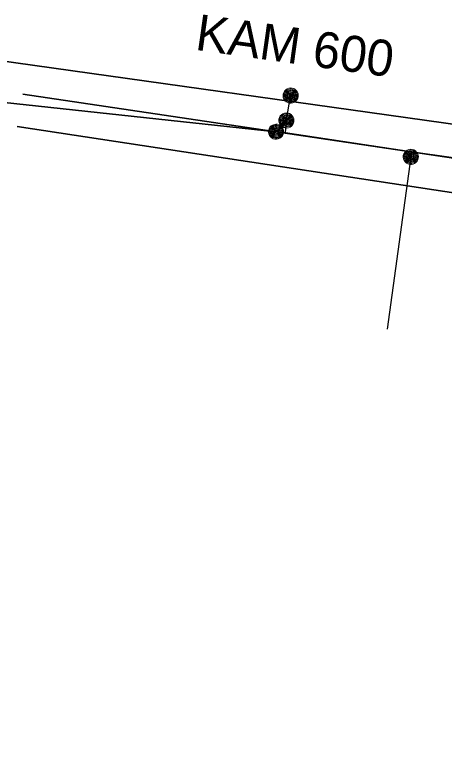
# Model space of a CAD drawing. Extents: x -866761 to -866592, y -1013996 to -1013877.
# Drawn here: x -866735.18 to -866722.08, y -1013979.36 to -1013957.16 of the extents above; entities that cross this region are included whole.
import ezdxf

# ---------------------------------------------------------------- set-up
doc = ezdxf.new("R2010")
doc.units = 0
doc.header["$LTSCALE"] = 0.44
doc.linetypes.add('DOT_DASHED', pattern=[7.7, 5, -1.2, 0.3, -1.2])
for name, color, linetype, lineweight in [('1', 7, 'Continuous', 35), ('12', 7, 'Continuous', 13), ('21', 7, 'Continuous', 35), ('3', 7, 'Continuous', 25), ('8', 7, 'Continuous', 13)]:
    doc.layers.add(name, color=color, linetype=linetype, lineweight=lineweight)

msp = doc.modelspace()

# ---------------------------------------------------------------- linework, layer by layer
at = {"layer": '1'}
msp.add_line((-866612.967, -1013977.763), (-866734.931, -1013959.586), dxfattribs=at)
for points in [[(-866612.815, -1013977.108), (-866621.035, -1013976.325), (-866621.378, -1013976.297), (-866626.243, -1013975.519), (-866632.94, -1013974.51), (-866645.03, -1013972.86), (-866647.305, -1013972.501), (-866654.48, -1013971.31), (-866668.882, -1013969.171), (-866678.229, -1013967.78), (-866685.446, -1013966.718), (-866689.8, -1013966.06), (-866697.865, -1013964.927), (-866723.097, -1013961.352), (-866726.923, -1013960.77), (-866727.214, -1013960.734), (-866737.38, -1013959.64), (-866746.09, -1013958.48), (-866747.84, -1013958.25), (-866748.13, -1013958.99), (-866750.15, -1013958.69)], [(-866613.338, -1013979.363), (-866624.951, -1013977.802), (-866715.256, -1013963.593), (-866735.102, -1013960.577)]]:
    msp.add_lwpolyline(points, dxfattribs=at)
at = {"layer": '1', "linetype": 'DOT_DASHED', "lineweight": 25}
msp.add_lwpolyline([(-866726.923, -1013960.77), (-866726.9, -1013960.39), (-866726.77, -1013959.63)], dxfattribs=at)
at = {"layer": '12'}
for points in [[(-866726.669, -1013960.39), (-866726.675, -1013960.338), (-866726.692, -1013960.288), (-866726.721, -1013960.244), (-866726.758, -1013960.207), (-866726.803, -1013960.18), (-866726.853, -1013960.163), (-866726.906, -1013960.159), (-866726.958, -1013960.166), (-866727.007, -1013960.185), (-866727.05, -1013960.214), (-866727.086, -1013960.253), (-866727.112, -1013960.298), (-866727.128, -1013960.349), (-866727.131, -1013960.401), (-866727.123, -1013960.453), (-866727.103, -1013960.502), (-866727.072, -1013960.545), (-866727.033, -1013960.579), (-866726.987, -1013960.605), (-866726.936, -1013960.619), (-866726.883, -1013960.621), (-866726.832, -1013960.611), (-866726.784, -1013960.59), (-866726.741, -1013960.559), (-866726.707, -1013960.518), (-866726.683, -1013960.472), (-866726.671, -1013960.421)], [(-866726.699, -1013960.39), (-866726.705, -1013960.341), (-866726.722, -1013960.295), (-866726.75, -1013960.255), (-866726.787, -1013960.223), (-866726.831, -1013960.201), (-866726.879, -1013960.19), (-866726.928, -1013960.19), (-866726.975, -1013960.203), (-866727.018, -1013960.227), (-866727.054, -1013960.26), (-866727.081, -1013960.301), (-866727.097, -1013960.348), (-866727.101, -1013960.397), (-866727.094, -1013960.445), (-866727.075, -1013960.49), (-866727.045, -1013960.53), (-866727.007, -1013960.561), (-866726.963, -1013960.581), (-866726.915, -1013960.591), (-866726.866, -1013960.589), (-866726.819, -1013960.574), (-866726.776, -1013960.549), (-866726.742, -1013960.515), (-866726.716, -1013960.473), (-866726.702, -1013960.426)], [(-866726.729, -1013960.39), (-866726.735, -1013960.345), (-866726.752, -1013960.303), (-866726.78, -1013960.268), (-866726.816, -1013960.241), (-866726.858, -1013960.224), (-866726.903, -1013960.219), (-866726.948, -1013960.225), (-866726.989, -1013960.244), (-866727.024, -1013960.272), (-866727.051, -1013960.309), (-866727.067, -1013960.351), (-866727.071, -1013960.396), (-866727.064, -1013960.441), (-866727.045, -1013960.482), (-866727.016, -1013960.516), (-866726.979, -1013960.542), (-866726.936, -1013960.558), (-866726.891, -1013960.561), (-866726.846, -1013960.553), (-866726.806, -1013960.533), (-866726.772, -1013960.504), (-866726.746, -1013960.466), (-866726.732, -1013960.423)], [(-866726.759, -1013960.39), (-866726.764, -1013960.349), (-866726.782, -1013960.312), (-866726.809, -1013960.281), (-866726.844, -1013960.26), (-866726.884, -1013960.249), (-866726.925, -1013960.251), (-866726.964, -1013960.264), (-866726.998, -1013960.288), (-866727.023, -1013960.32), (-866727.038, -1013960.358), (-866727.041, -1013960.399), (-866727.033, -1013960.439), (-866727.013, -1013960.475), (-866726.984, -1013960.504), (-866726.947, -1013960.523), (-866726.907, -1013960.531), (-866726.866, -1013960.527), (-866726.828, -1013960.512), (-866726.796, -1013960.486), (-866726.773, -1013960.452), (-866726.76, -1013960.413)], [(-866726.789, -1013960.39), (-866726.794, -1013960.354), (-866726.812, -1013960.322), (-866726.838, -1013960.297), (-866726.872, -1013960.282), (-866726.908, -1013960.279), (-866726.943, -1013960.287), (-866726.974, -1013960.307), (-866726.997, -1013960.335), (-866727.01, -1013960.369), (-866727.01, -1013960.406), (-866726.999, -1013960.441), (-866726.978, -1013960.47), (-866726.948, -1013960.491), (-866726.913, -1013960.501), (-866726.876, -1013960.499), (-866726.842, -1013960.485), (-866726.815, -1013960.462), (-866726.796, -1013960.43), (-866726.789, -1013960.395)], [(-866726.819, -1013960.39), (-866726.824, -1013960.359), (-866726.841, -1013960.333), (-866726.867, -1013960.316), (-866726.897, -1013960.309), (-866726.928, -1013960.313), (-866726.955, -1013960.33), (-866726.973, -1013960.354), (-866726.981, -1013960.385), (-866726.977, -1013960.415), (-866726.962, -1013960.443), (-866726.938, -1013960.462), (-866726.908, -1013960.471), (-866726.877, -1013960.468), (-866726.849, -1013960.454), (-866726.829, -1013960.43), (-866726.819, -1013960.401)], [(-866726.849, -1013960.39), (-866726.854, -1013960.366), (-866726.871, -1013960.348), (-866726.894, -1013960.339), (-866726.918, -1013960.342), (-866726.939, -1013960.356), (-866726.95, -1013960.378), (-866726.95, -1013960.403), (-866726.938, -1013960.424), (-866726.918, -1013960.438), (-866726.893, -1013960.441), (-866726.87, -1013960.432), (-866726.854, -1013960.414)], [(-866726.879, -1013960.39), (-866726.884, -1013960.375), (-866726.899, -1013960.369), (-866726.914, -1013960.373), (-866726.921, -1013960.387), (-866726.917, -1013960.402), (-866726.904, -1013960.411), (-866726.889, -1013960.408), (-866726.879, -1013960.396)], [(-866726.983, -1013960.734), (-866726.989, -1013960.682), (-866727.006, -1013960.632), (-866727.035, -1013960.588), (-866727.072, -1013960.551), (-866727.117, -1013960.524), (-866727.167, -1013960.507), (-866727.22, -1013960.503), (-866727.272, -1013960.51), (-866727.321, -1013960.529), (-866727.364, -1013960.558), (-866727.4, -1013960.597), (-866727.426, -1013960.642), (-866727.442, -1013960.693), (-866727.445, -1013960.745), (-866727.437, -1013960.797), (-866727.417, -1013960.846), (-866727.386, -1013960.889), (-866727.347, -1013960.923), (-866727.301, -1013960.949), (-866727.25, -1013960.963), (-866727.197, -1013960.965), (-866727.146, -1013960.955), (-866727.098, -1013960.934), (-866727.055, -1013960.903), (-866727.021, -1013960.862), (-866726.997, -1013960.816), (-866726.985, -1013960.765)], [(-866727.013, -1013960.734), (-866727.019, -1013960.685), (-866727.036, -1013960.639), (-866727.064, -1013960.599), (-866727.101, -1013960.567), (-866727.145, -1013960.545), (-866727.193, -1013960.534), (-866727.242, -1013960.534), (-866727.289, -1013960.547), (-866727.332, -1013960.571), (-866727.368, -1013960.604), (-866727.395, -1013960.645), (-866727.411, -1013960.692), (-866727.415, -1013960.741), (-866727.408, -1013960.789), (-866727.389, -1013960.834), (-866727.359, -1013960.874), (-866727.321, -1013960.905), (-866727.277, -1013960.925), (-866727.229, -1013960.935), (-866727.18, -1013960.933), (-866727.133, -1013960.918), (-866727.09, -1013960.893), (-866727.056, -1013960.859), (-866727.03, -1013960.817), (-866727.016, -1013960.77)], [(-866727.043, -1013960.734), (-866727.049, -1013960.689), (-866727.066, -1013960.647), (-866727.094, -1013960.612), (-866727.13, -1013960.585), (-866727.172, -1013960.568), (-866727.217, -1013960.563), (-866727.262, -1013960.569), (-866727.303, -1013960.588), (-866727.338, -1013960.616), (-866727.365, -1013960.653), (-866727.381, -1013960.695), (-866727.385, -1013960.74), (-866727.378, -1013960.785), (-866727.359, -1013960.826), (-866727.33, -1013960.86), (-866727.293, -1013960.886), (-866727.25, -1013960.902), (-866727.205, -1013960.905), (-866727.16, -1013960.897), (-866727.12, -1013960.877), (-866727.086, -1013960.848), (-866727.06, -1013960.81), (-866727.046, -1013960.767)], [(-866727.073, -1013960.734), (-866727.078, -1013960.693), (-866727.096, -1013960.656), (-866727.123, -1013960.625), (-866727.158, -1013960.604), (-866727.198, -1013960.593), (-866727.239, -1013960.595), (-866727.278, -1013960.608), (-866727.312, -1013960.632), (-866727.337, -1013960.664), (-866727.352, -1013960.702), (-866727.355, -1013960.743), (-866727.347, -1013960.783), (-866727.327, -1013960.819), (-866727.298, -1013960.848), (-866727.261, -1013960.867), (-866727.221, -1013960.875), (-866727.18, -1013960.871), (-866727.142, -1013960.856), (-866727.11, -1013960.83), (-866727.087, -1013960.796), (-866727.074, -1013960.757)], [(-866727.103, -1013960.734), (-866727.108, -1013960.698), (-866727.126, -1013960.666), (-866727.152, -1013960.641), (-866727.186, -1013960.626), (-866727.222, -1013960.623), (-866727.257, -1013960.631), (-866727.288, -1013960.651), (-866727.311, -1013960.679), (-866727.324, -1013960.713), (-866727.324, -1013960.75), (-866727.313, -1013960.785), (-866727.292, -1013960.814), (-866727.262, -1013960.835), (-866727.227, -1013960.845), (-866727.19, -1013960.843), (-866727.156, -1013960.829), (-866727.129, -1013960.806), (-866727.11, -1013960.774), (-866727.103, -1013960.739)], [(-866727.133, -1013960.734), (-866727.138, -1013960.703), (-866727.155, -1013960.677), (-866727.181, -1013960.66), (-866727.211, -1013960.653), (-866727.242, -1013960.657), (-866727.269, -1013960.674), (-866727.287, -1013960.698), (-866727.295, -1013960.729), (-866727.291, -1013960.759), (-866727.276, -1013960.787), (-866727.252, -1013960.806), (-866727.222, -1013960.815), (-866727.191, -1013960.812), (-866727.163, -1013960.798), (-866727.143, -1013960.774), (-866727.133, -1013960.745)], [(-866727.163, -1013960.734), (-866727.168, -1013960.71), (-866727.185, -1013960.692), (-866727.208, -1013960.683), (-866727.232, -1013960.686), (-866727.253, -1013960.7), (-866727.264, -1013960.722), (-866727.264, -1013960.747), (-866727.252, -1013960.768), (-866727.232, -1013960.782), (-866727.207, -1013960.785), (-866727.184, -1013960.776), (-866727.168, -1013960.758)], [(-866727.193, -1013960.734), (-866727.198, -1013960.719), (-866727.213, -1013960.713), (-866727.228, -1013960.717), (-866727.235, -1013960.731), (-866727.231, -1013960.746), (-866727.218, -1013960.755), (-866727.203, -1013960.752), (-866727.193, -1013960.74)], [(-866722.879, -1013961.5), (-866722.885, -1013961.448), (-866722.902, -1013961.398), (-866722.931, -1013961.354), (-866722.968, -1013961.317), (-866723.013, -1013961.29), (-866723.063, -1013961.273), (-866723.116, -1013961.269), (-866723.168, -1013961.276), (-866723.217, -1013961.295), (-866723.26, -1013961.324), (-866723.296, -1013961.363), (-866723.322, -1013961.408), (-866723.338, -1013961.459), (-866723.341, -1013961.511), (-866723.333, -1013961.563), (-866723.313, -1013961.612), (-866723.282, -1013961.655), (-866723.243, -1013961.689), (-866723.197, -1013961.715), (-866723.146, -1013961.729), (-866723.093, -1013961.731), (-866723.042, -1013961.721), (-866722.994, -1013961.7), (-866722.951, -1013961.669), (-866722.917, -1013961.628), (-866722.893, -1013961.582), (-866722.88, -1013961.531)], [(-866722.909, -1013961.5), (-866722.915, -1013961.451), (-866722.932, -1013961.405), (-866722.96, -1013961.365), (-866722.997, -1013961.333), (-866723.041, -1013961.311), (-866723.089, -1013961.3), (-866723.138, -1013961.3), (-866723.184, -1013961.313), (-866723.228, -1013961.337), (-866723.264, -1013961.37), (-866723.291, -1013961.411), (-866723.307, -1013961.458), (-866723.311, -1013961.507), (-866723.304, -1013961.555), (-866723.285, -1013961.6), (-866723.255, -1013961.64), (-866723.217, -1013961.671), (-866723.173, -1013961.691), (-866723.125, -1013961.701), (-866723.076, -1013961.699), (-866723.029, -1013961.684), (-866722.986, -1013961.659), (-866722.951, -1013961.625), (-866722.926, -1013961.583), (-866722.912, -1013961.536)], [(-866722.939, -1013961.5), (-866722.945, -1013961.455), (-866722.962, -1013961.413), (-866722.99, -1013961.378), (-866723.026, -1013961.351), (-866723.068, -1013961.334), (-866723.113, -1013961.329), (-866723.157, -1013961.335), (-866723.199, -1013961.354), (-866723.233, -1013961.382), (-866723.261, -1013961.419), (-866723.277, -1013961.461), (-866723.281, -1013961.506), (-866723.274, -1013961.551), (-866723.255, -1013961.592), (-866723.226, -1013961.626), (-866723.189, -1013961.652), (-866723.146, -1013961.668), (-866723.101, -1013961.671), (-866723.056, -1013961.663), (-866723.016, -1013961.643), (-866722.982, -1013961.614), (-866722.956, -1013961.576), (-866722.942, -1013961.533)], [(-866722.969, -1013961.5), (-866722.973, -1013961.459), (-866722.992, -1013961.422), (-866723.019, -1013961.391), (-866723.054, -1013961.37), (-866723.094, -1013961.359), (-866723.135, -1013961.361), (-866723.174, -1013961.374), (-866723.208, -1013961.398), (-866723.233, -1013961.43), (-866723.248, -1013961.468), (-866723.25, -1013961.509), (-866723.243, -1013961.549), (-866723.223, -1013961.585), (-866723.194, -1013961.614), (-866723.157, -1013961.633), (-866723.117, -1013961.641), (-866723.076, -1013961.637), (-866723.038, -1013961.622), (-866723.005, -1013961.596), (-866722.983, -1013961.562), (-866722.97, -1013961.523)], [(-866722.999, -1013961.5), (-866723.004, -1013961.464), (-866723.022, -1013961.432), (-866723.048, -1013961.407), (-866723.081, -1013961.392), (-866723.118, -1013961.389), (-866723.152, -1013961.397), (-866723.184, -1013961.417), (-866723.206, -1013961.445), (-866723.22, -1013961.479), (-866723.22, -1013961.516), (-866723.209, -1013961.551), (-866723.188, -1013961.58), (-866723.157, -1013961.601), (-866723.123, -1013961.611), (-866723.086, -1013961.609), (-866723.052, -1013961.595), (-866723.025, -1013961.572), (-866723.005, -1013961.54), (-866722.999, -1013961.505)], [(-866723.029, -1013961.5), (-866723.034, -1013961.469), (-866723.051, -1013961.443), (-866723.076, -1013961.426), (-866723.107, -1013961.419), (-866723.138, -1013961.423), (-866723.165, -1013961.44), (-866723.183, -1013961.464), (-866723.191, -1013961.495), (-866723.187, -1013961.525), (-866723.172, -1013961.553), (-866723.147, -1013961.572), (-866723.118, -1013961.581), (-866723.087, -1013961.578), (-866723.059, -1013961.564), (-866723.039, -1013961.54), (-866723.029, -1013961.511)], [(-866723.059, -1013961.5), (-866723.064, -1013961.476), (-866723.081, -1013961.458), (-866723.103, -1013961.449), (-866723.128, -1013961.452), (-866723.149, -1013961.466), (-866723.16, -1013961.488), (-866723.16, -1013961.513), (-866723.147, -1013961.534), (-866723.128, -1013961.548), (-866723.103, -1013961.551), (-866723.08, -1013961.542), (-866723.064, -1013961.524)], [(-866723.089, -1013961.5), (-866723.094, -1013961.485), (-866723.108, -1013961.479), (-866723.124, -1013961.483), (-866723.13, -1013961.497), (-866723.127, -1013961.512), (-866723.114, -1013961.521), (-866723.098, -1013961.518), (-866723.089, -1013961.506)]]:
    msp.add_lwpolyline(points, close=True, dxfattribs=at)
at = {"layer": '21'}
msp.add_line((-866743.07, -1013957.51), (-866709.04, -1013962.31), dxfattribs=at)
at = {"layer": '3'}
msp.add_lwpolyline([(-866723.097, -1013961.352), (-866723.11, -1013961.5), (-866723.825, -1013966.752)], dxfattribs=at)
at = {"layer": '8'}
for points in [[(-866726.539, -1013959.63), (-866726.545, -1013959.578), (-866726.562, -1013959.528), (-866726.591, -1013959.484), (-866726.628, -1013959.447), (-866726.673, -1013959.42), (-866726.723, -1013959.403), (-866726.776, -1013959.399), (-866726.828, -1013959.406), (-866726.877, -1013959.425), (-866726.92, -1013959.454), (-866726.956, -1013959.493), (-866726.982, -1013959.538), (-866726.998, -1013959.589), (-866727.001, -1013959.641), (-866726.993, -1013959.693), (-866726.973, -1013959.742), (-866726.942, -1013959.785), (-866726.903, -1013959.819), (-866726.857, -1013959.845), (-866726.806, -1013959.859), (-866726.753, -1013959.861), (-866726.702, -1013959.851), (-866726.654, -1013959.83), (-866726.611, -1013959.799), (-866726.577, -1013959.758), (-866726.553, -1013959.712), (-866726.541, -1013959.661)], [(-866726.569, -1013959.63), (-866726.575, -1013959.581), (-866726.592, -1013959.535), (-866726.62, -1013959.495), (-866726.657, -1013959.463), (-866726.701, -1013959.441), (-866726.749, -1013959.43), (-866726.798, -1013959.43), (-866726.845, -1013959.443), (-866726.888, -1013959.467), (-866726.924, -1013959.5), (-866726.951, -1013959.541), (-866726.967, -1013959.588), (-866726.971, -1013959.637), (-866726.964, -1013959.685), (-866726.945, -1013959.73), (-866726.915, -1013959.77), (-866726.877, -1013959.801), (-866726.833, -1013959.821), (-866726.785, -1013959.831), (-866726.736, -1013959.829), (-866726.689, -1013959.814), (-866726.646, -1013959.789), (-866726.612, -1013959.755), (-866726.586, -1013959.713), (-866726.572, -1013959.666)], [(-866726.599, -1013959.63), (-866726.605, -1013959.585), (-866726.622, -1013959.543), (-866726.65, -1013959.508), (-866726.686, -1013959.481), (-866726.728, -1013959.464), (-866726.773, -1013959.459), (-866726.818, -1013959.465), (-866726.859, -1013959.484), (-866726.894, -1013959.512), (-866726.921, -1013959.549), (-866726.937, -1013959.591), (-866726.941, -1013959.636), (-866726.934, -1013959.681), (-866726.915, -1013959.722), (-866726.886, -1013959.756), (-866726.849, -1013959.782), (-866726.806, -1013959.798), (-866726.761, -1013959.801), (-866726.716, -1013959.793), (-866726.676, -1013959.773), (-866726.642, -1013959.744), (-866726.616, -1013959.706), (-866726.602, -1013959.663)], [(-866726.629, -1013959.63), (-866726.634, -1013959.589), (-866726.652, -1013959.552), (-866726.679, -1013959.521), (-866726.714, -1013959.5), (-866726.754, -1013959.489), (-866726.795, -1013959.491), (-866726.834, -1013959.504), (-866726.868, -1013959.528), (-866726.893, -1013959.56), (-866726.908, -1013959.598), (-866726.911, -1013959.639), (-866726.903, -1013959.679), (-866726.883, -1013959.715), (-866726.854, -1013959.744), (-866726.817, -1013959.763), (-866726.777, -1013959.771), (-866726.736, -1013959.767), (-866726.698, -1013959.752), (-866726.666, -1013959.726), (-866726.643, -1013959.692), (-866726.63, -1013959.653)], [(-866726.659, -1013959.63), (-866726.664, -1013959.594), (-866726.682, -1013959.562), (-866726.708, -1013959.537), (-866726.742, -1013959.522), (-866726.778, -1013959.519), (-866726.813, -1013959.527), (-866726.844, -1013959.547), (-866726.867, -1013959.575), (-866726.88, -1013959.609), (-866726.88, -1013959.646), (-866726.869, -1013959.681), (-866726.848, -1013959.71), (-866726.818, -1013959.731), (-866726.783, -1013959.741), (-866726.746, -1013959.739), (-866726.712, -1013959.725), (-866726.685, -1013959.702), (-866726.666, -1013959.67), (-866726.659, -1013959.635)], [(-866726.689, -1013959.63), (-866726.694, -1013959.599), (-866726.711, -1013959.573), (-866726.737, -1013959.556), (-866726.767, -1013959.549), (-866726.798, -1013959.553), (-866726.825, -1013959.57), (-866726.843, -1013959.594), (-866726.851, -1013959.625), (-866726.847, -1013959.655), (-866726.832, -1013959.683), (-866726.808, -1013959.702), (-866726.778, -1013959.711), (-866726.747, -1013959.708), (-866726.719, -1013959.694), (-866726.699, -1013959.67), (-866726.689, -1013959.641)], [(-866726.719, -1013959.63), (-866726.724, -1013959.606), (-866726.741, -1013959.588), (-866726.764, -1013959.579), (-866726.788, -1013959.582), (-866726.809, -1013959.596), (-866726.82, -1013959.618), (-866726.82, -1013959.643), (-866726.808, -1013959.664), (-866726.788, -1013959.678), (-866726.763, -1013959.681), (-866726.74, -1013959.672), (-866726.724, -1013959.654)], [(-866726.749, -1013959.63), (-866726.754, -1013959.615), (-866726.769, -1013959.609), (-866726.784, -1013959.613), (-866726.791, -1013959.627), (-866726.787, -1013959.642), (-866726.774, -1013959.651), (-866726.759, -1013959.648), (-866726.749, -1013959.636)]]:
    msp.add_lwpolyline(points, close=True, dxfattribs=at)

# ---------------------------------------------------------------- texts
at = {"layer": '1'}
msp.add_text('KAM 600 ', height=1.1, rotation=352, dxfattribs=at).set_placement((-866729.706, -1013958.232))

doc.saveas('drawing.dxf')
